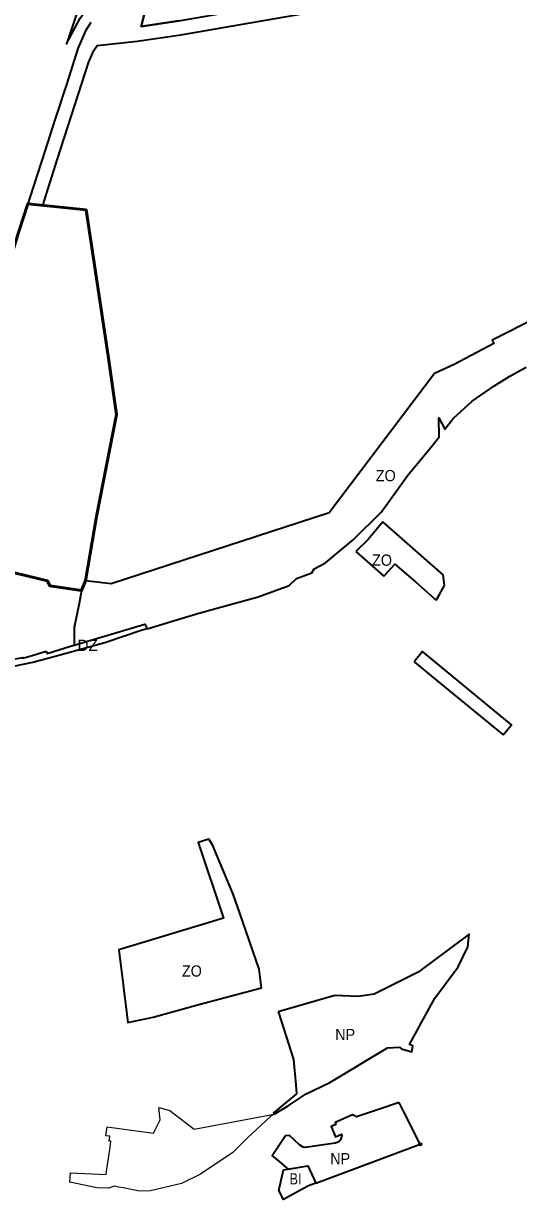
# Model space of a CAD drawing. Extents: x -650276 to -642489, y -1074311 to -1066658.
# Drawn here: x -646647 to -646121, y -1070418 to -1069166 of the extents above; entities that cross this region are included whole.
import ezdxf

# ---------------------------------------------------------------- set-up
doc = ezdxf.new("R2010")
doc.units = 0
doc.header["$LTSCALE"] = 4.8
doc.header["$PDMODE"] = 32
doc.header["$PDSIZE"] = 2.4
for name, color, linetype, lineweight in [('15', 7, 'Continuous', 35), ('2', 7, 'Continuous', 35), ('24', 7, 'Continuous', 35), ('25', 7, 'Continuous', 35), ('34', 7, 'Continuous', 35), ('42', 7, 'Continuous', 35), ('48', 7, 'Continuous', 35), ('60', 7, 'Continuous', 53), ('61', 7, 'Continuous', 25)]:
    doc.layers.add(name, color=color, linetype=linetype, lineweight=lineweight)
doc.layers.add('62', color=7, linetype='Continuous')

msp = doc.modelspace()

# ---------------------------------------------------------------- linework, layer by layer
at = {"layer": '15'}
msp.add_line((-646142.68, -1069918.62), (-646136.88, -1069923.39), dxfattribs=at)
for points in [[(-646136.88, -1069923.39), (-646127.987, -1069912.574), (-646222.694, -1069834.722), (-646231.73, -1069845.42)], [(-646231.73, -1069845.42), (-646203.48, -1069868.65), (-646142.68, -1069918.62)]]:
    msp.add_lwpolyline(points, dxfattribs=at)
at = {"layer": '2'}
msp.add_lwpolyline([(-646344.93, -1070382.33), (-646336.25, -1070400.875), (-646344.26, -1070403.84), (-646359.769, -1070412.361), (-646370.56, -1070418.29), (-646375.63, -1070408.76), (-646370.624, -1070386.792)], close=True, dxfattribs=at)
at = {"layer": '24'}
msp.add_lwpolyline([(-646582.46, -1069152.81), (-646575.4, -1069141.46), (-646564.54, -1069125.08), (-646562.35, -1069106.21), (-646561.88, -1069102.18), (-646555.84, -1069050.22), (-646555.84, -1069050.22), (-646559.8, -1069048.98), (-646562.61, -1069048.08), (-646566.82, -1069083.62), (-646601.82, -1069187.25), (-646586.97, -1069160.06), (-646585.42, -1069157.56), (-646583.89, -1069155.1), (-646582.46, -1069152.81)], close=True, dxfattribs=at)
at = {"layer": '25'}
for points in [[(-646593.34, -1069827.68), (-646518.19, -1069805.27), (-646515.63, -1069810.24)], [(-646515.63, -1069810.24), (-646522.32, -1069812.28), (-646560.92, -1069825.33), (-646613.65, -1069840.02), (-646620.06, -1069841.69), (-646629.83, -1069844.23), (-646635.93, -1069845.82), (-646658.5, -1069850.59), (-646689.73, -1069854.58), (-646705.87, -1069856.62), (-646717.66, -1069857.11), (-646729.54, -1069853.69)], [(-646623.31, -1069834.1), (-646622.54, -1069835.88), (-646622.19, -1069836.71), (-646597.29, -1069828.86), (-646593.34, -1069827.68)], [(-646729.24, -1069851.41), (-646723.5, -1069852.83), (-646719.82, -1069853.78), (-646689.63, -1069849.7), (-646689.8, -1069848.71), (-646664.22, -1069843.72), (-646648.18, -1069841.04), (-646648.28, -1069841.78), (-646638.34, -1069838.73), (-646623.31, -1069834.1)]]:
    msp.add_lwpolyline(points, dxfattribs=at)
at = {"layer": '34'}
msp.add_lwpolyline([(-646161.484, -1069046.228), (-646238.632, -1068916.799), (-646266.118, -1068883.048), (-646277.268, -1068890.446), (-646292.75, -1068900.72), (-646344.49, -1068948.736), (-646268.528, -1069036.82), (-646290.099, -1069055.423), (-646352.71, -1068981.82), (-646386.936, -1069012.936), (-646375.346, -1069032.07), (-646379.973, -1069035.889), (-646393.09, -1069014.234), (-646404.269, -1069001.033), (-646425.52, -1069019.41), (-646449.418, -1069039.804), (-646474.13, -1069055.83), (-646488.537, -1069062.169), (-646495.89, -1069063.531), (-646522.35, -1069168.648), (-646482.211, -1069162.813), (-646256.824, -1069123.414)], close=True, dxfattribs=at)
at = {"layer": '42'}
msp.add_line((-646230.3, -1069760.5), (-646208.135, -1069779.937), dxfattribs=at)
for points in [[(-646482.211, -1069162.813), (-646522.35, -1069168.648), (-646495.89, -1069063.531)], [(-646575.87, -1069164.54), (-646581.29, -1069173.32), (-646589.56, -1069192.07), (-646601.41, -1069229.34), (-646613.6, -1069267.04), (-646627.59, -1069310.34), (-646628.66, -1069313.66), (-646640.715, -1069350.951), (-646642.89, -1069357.68), (-646626.774, -1069359.349), (-646611.107, -1069309.68), (-646577.878, -1069206.485), (-646572.586, -1069194.485), (-646569.114, -1069188.86), (-646526.31, -1069184.381), (-646479.84, -1069177.626), (-646250.409, -1069137.52)], [(-646023.96, -1069440.34), (-646028.16, -1069441.58), (-646080.35, -1069469.89), (-646102.15, -1069479.49), (-646148.5, -1069503), (-646146.8, -1069506.6), (-646189.17, -1069528.74), (-646209.9, -1069538.5), (-646321.973, -1069686.855), (-646554.262, -1069762.602), (-646581.489, -1069759.421), (-646585.51, -1069769.57)], [(-646491.18, -1069802.78), (-646491.18, -1069802.78), (-646460.97, -1069793.56), (-646397.74, -1069776.29), (-646364.67, -1069764.23), (-646357, -1069756.7), (-646340.48, -1069750.92), (-646337.97, -1069746.4), (-646325.92, -1069740.05), (-646296.64, -1069715.72), (-646266.27, -1069685.75), (-646250, -1069663.09), (-646238.19, -1069646.63), (-646212.43, -1069615.33), (-646210.03, -1069612.42), (-646205.9, -1069607.17), (-646205, -1069606.03), (-646205.25, -1069585.67), (-646198.82, -1069597.83), (-646190.07, -1069586.48), (-646169.9, -1069568.04), (-646146.81, -1069551.97), (-646129.87, -1069541.19), (-646112.56, -1069531.78)], [(-646265.02, -1069696.43), (-646280.5, -1069715.27), (-646293.76, -1069728)], [(-646208.135, -1069779.937), (-646204.6, -1069773.78), (-646199.17, -1069764.33), (-646200.67, -1069752.88), (-646265.02, -1069696.43)], [(-646293.76, -1069728), (-646263.929, -1069754.309), (-646263.36, -1069753.69), (-646252.07, -1069741.41), (-646230.3, -1069760.5)], [(-646585.51, -1069769.57), (-646588.25, -1069783.37), (-646593.34, -1069808.99), (-646593.34, -1069827.68)], [(-646593.34, -1069827.68), (-646518.19, -1069805.27), (-646515.63, -1069810.24), (-646491.18, -1069802.78)], [(-646417.23, -1070113.25), (-646424.17, -1070093.21), (-646446.21, -1070040.55), (-646450.22, -1070034.31), (-646461.415, -1070037.991), (-646434.503, -1070118.512), (-646545.78, -1070152.41), (-646536.47, -1070229.65), (-646509.31, -1070224.11), (-646460.8, -1070210.57)], [(-646460.8, -1070210.57), (-646393.97, -1070192.69), (-646396.51, -1070173.06), (-646417.23, -1070113.25)]]:
    msp.add_lwpolyline(points, dxfattribs=at)
at = {"layer": '48'}
for points in [[(-646376.5, -1070218.32), (-646375.52, -1070220.21), (-646359.89, -1070269.01), (-646357.73, -1070296.13), (-646356.8, -1070305.73), (-646381.25, -1070325.85), (-646380.69, -1070327.47), (-646365.63, -1070318.37), (-646346.57, -1070305.88), (-646321.24, -1070293.85), (-646259.91, -1070256.89), (-646246.71, -1070255.96), (-646245.02, -1070257.65), (-646234.17, -1070260.88), (-646233.69, -1070259.57), (-646233.36, -1070257.04), (-646233.06, -1070254.74), (-646236.44, -1070253.13), (-646226.42, -1070234.23), (-646225.7, -1070232.93), (-646209.55, -1070203.85), (-646184.67, -1070170.61), (-646174.62, -1070149.28), (-646173.2, -1070135.64), (-646227.29, -1070176.24), (-646274.26, -1070199.6), (-646291.14, -1070202.1), (-646315.95, -1070201.09)], [(-646247.667, -1070315.004), (-646267.3, -1070321.61), (-646293.14, -1070330.3), (-646297.4, -1070328.01), (-646315.84, -1070336.13), (-646314.84, -1070338.41), (-646319.95, -1070340.42), (-646315.46, -1070351.67), (-646308.791, -1070348.855), (-646308.59, -1070350.22), (-646309.18, -1070352.77), (-646309.99, -1070354.58), (-646311.82, -1070356.89), (-646314.6, -1070358.05), (-646315.7, -1070358.27), (-646347.49, -1070363.01), (-646349.76, -1070362.69), (-646353.81, -1070360.18), (-646364.34, -1070350.19), (-646368.4, -1070350.41), (-646382.67, -1070371.94), (-646377.86, -1070375.71), (-646365.7, -1070385.89), (-646344.93, -1070382.33), (-646336.35, -1070400.9), (-646225.15, -1070359.46), (-646242.56, -1070325.1)]]:
    msp.add_lwpolyline(points, close=True, dxfattribs=at)
msp.add_point((-646225.15, -1070359.46), dxfattribs=at)
at = {"layer": '60'}
msp.add_lwpolyline([(-646695.61, -1069583.8), (-646698.4, -1069578.93), (-646684.95, -1069502.53), (-646679.13, -1069473.51), (-646652.72, -1069388.08), (-646642.89, -1069357.68), (-646580.797, -1069364.111), (-646557.39, -1069519.61), (-646548.41, -1069582.03), (-646569.86, -1069690.67), (-646581.489, -1069759.421), (-646585.51, -1069769.57), (-646619.49, -1069764.46), (-646622, -1069759.34), (-646679.46, -1069745.37), (-646677.36, -1069733.65), (-646680.28, -1069714.83), (-646673, -1069676.8), (-646666.26, -1069641.2), (-646659.52, -1069605.53), (-646666.36, -1069588.57), (-646698.96, -1069582.26)], dxfattribs=at)
at = {"layer": '61'}
msp.add_lwpolyline([(-646503.36, -1070320.39), (-646491.81, -1070323.54), (-646481.1, -1070331.76), (-646465.85, -1070343.46), (-646380.69, -1070327.47), (-646384.18, -1070329.58), (-646408.97, -1070352.57), (-646422.07, -1070365.6), (-646424.74, -1070368.25), (-646459.18, -1070391.48), (-646479.26, -1070401.17), (-646512.38, -1070409.18), (-646523.89, -1070409.54), (-646541.25, -1070406.02), (-646545.97, -1070405.06), (-646550.91, -1070404.27), (-646556.66, -1070406.07), (-646569.39, -1070406.06), (-646598.16, -1070399.848), (-646597.44, -1070389.891), (-646559.41, -1070391.82), (-646558.74, -1070386.15), (-646556, -1070367.59), (-646554.86, -1070359.63), (-646554.86, -1070359.63), (-646554.42, -1070356.22), (-646556.1, -1070356), (-646555.42, -1070350.94), (-646559.71, -1070350.35), (-646558.49, -1070340.9), (-646545.77, -1070342.7), (-646509.08, -1070347.79), (-646505.44, -1070340.51), (-646501.94, -1070333.51)], close=True, dxfattribs=at)

# ---------------------------------------------------------------- texts
at = {"layer": '62'}
for s, width, p in [('ZO', 0.95, (-646272.423, -1069653.188)), ('ZO', 0.95, (-646276.423, -1069743.188)), ('ZO', 0.95, (-646478.758, -1070180.853)), ('NP', 0.95, (-646315.631, -1070248.579)), ('NP', 0.95, (-646320.99, -1070380.819)), ('BI', 0.85, (-646364.337, -1070402.32))]:
    msp.add_text(s, height=12, dxfattribs=dict(at, width=width)).set_placement(p)
msp.add_text('DZ', height=12, dxfattribs=at).set_placement((-646589.843, -1069833.949))

doc.saveas('drawing.dxf')
